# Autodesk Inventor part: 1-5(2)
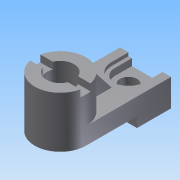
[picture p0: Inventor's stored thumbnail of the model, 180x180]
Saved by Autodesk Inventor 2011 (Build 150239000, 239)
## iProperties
Created: 2014-02
Part Number: 1-5(2)
Document SubType Name: Modeling
Designer: Administrator
Density: 1 g/cm^3
Author: Administrator
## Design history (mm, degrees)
sketch "草图1"
  geometry: C1 r 7.5 at (0, 0); 1 further point
  constraints: 1 centre point, 1 coincident
  dimensions: "d0" = 15 diameter of C1
extrude "拉伸1" new body sketch "草图1" distance "d1" = 15; taper "d2" = 0 deg
sketch "草图2"
  geometry: L1 (-7.5, 0)-(7.5, 0); L2 (7.5, 0)-(7.5, 25); L3 (7.5, 25)-(-7.5, 25); L4 (-7.5, 25)-(-7.5, 0); 1 further point
  constraints: 8 end point, 2 parallel, 1 horizontal, 1 horizontal alignment, 1 perpendicular, 1 other
  dimensions: "d3" = 25 distance of L1.end L2.end
extrude "拉伸2" join sketch "草图2" distance "d4" = 5; taper "d5" = 0 deg
sketch "草图3"
  geometry: L1 (7.5, 25)-(-7.5, 25) reference; L2 (7.5, 0)-(7.5, 25) reference; L3 (-7.5, 25)-(-7.5, 0) reference; L4 (-7.5, 15)-(7.5, 15); L5 (-7.5, 15)-(-7.5, 25); L6 (7.5, 25)-(7.5, 15); 3 further points
  constraints: 6 end point, 4 point on line, 2 collinear, 1 midpoint, 1 perpendicular
extrude "拉伸3" join sketch "草图3" distance "d7" = 3; taper "d8" = 0 deg
sketch "草图4"
  geometry: C1 r 2.5 at (0, 20); 1 further point
  constraints: 1 centre point
  dimensions: "d9" = 5 diameter of C1
extrude "拉伸4" cut sketch "草图4" distance "d10" = 10; taper "d11" = 0 deg
sketch "草图5"
  geometry: C1 r 7.5 at (0, 0) reference; C2 r 4 at (0, 0)
  constraints: 1 centre point, 1 coincident
  dimensions: "d12" = 8 diameter of C2
extrude "拉伸5" cut sketch "草图5" stored distance "d13" = 10; taper "d14" = 0 deg
sketch "草图6"
  geometry: L1 (-7.5, 25)-(7.5, 25) reference; L2 (-5, 20)-(-5, 25); L3 (5, 20)-(5, 25); C1 r 2.5 at (0, 20) reference; A1 r 5 centre (0, 20) between (-5, 20) and (5, 20) reference; A2 r 5 centre (0, 20) between (-5, 20) and (5, 20)
  constraints: 4 end point, 4 tangent, 3 point on line, 2 perpendicular, 2 point on circle, 1 centre point, 1 coincident
extrude "拉伸6" cut sketch "草图6" distance "d15" = 1; taper "d16" = 0 deg
sketch "草图7"
  geometry: L1 (-5, 25)-(5, 25) reference; L2 (-4, 20)-(-4, 25); L3 (4, 20)-(4, 25); C1 r 2.5 at (0, 20) reference; A1 r 5 centre (0, 20) between (-5, 20) and (5, 20) reference; A2 r 4 centre (0, 20) between (-4, 20) and (4, 20); 1 further point
  constraints: 4 end point, 2 perpendicular, 2 point on circle, 2 point on line, 2 tangent, 1 centre point, 1 coincident
  dimensions: "d17" = 8 diameter of A2
extrude "拉伸7" cut sketch "草图7" distance "d18" = 2; taper "d19" = 0 deg
sketch "草图8"
  geometry: L1 (-8.089, -1.5)-(8.021, -1.5); L2 (8.021, -1.5)-(8.021, 1.5); L3 (8.021, 1.5)-(-8.089, 1.5); L4 (-8.089, 1.5)-(-8.089, -1.5); C1 r 4 at (0, 0) reference; 1 further point
  constraints: 8 end point, 2 parallel, 1 horizontal, 1 horizontal alignment, 1 midpoint, 1 perpendicular
  dimensions: "d21" = 3 distance of L1.end L2.end
extrude "拉伸8" cut sketch "草图8" distance "d22" = 2; taper "d23" = 0 deg
hole "Hole1" diameter "d26" = 12; stored, may be unused: countersink angle "d30" = 90 deg, drill point angle "d32" = 0 deg; dims "d24" = 10, "d25" = 10, "d27" = 6, "d28" = 4, "d29" = 2, "d31" = 3
sketch "草图9"
  geometry: L1 (7.5, 5)-(7.5, 15) reference; L2 (0, 5)-(25, 5) reference; L3 (6.893, 13.447)-(13.57, 5); 1 further point
  constraints: 2 end point, 1 point on line
feature "加强筋1" sketch "草图9" dims "d33" = 1, "d34" = 3, "d35" = 0
node "实体1"
